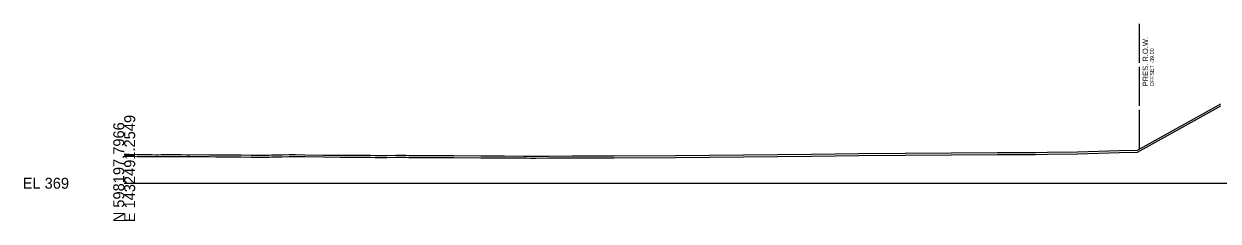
# Model space of a CAD drawing. Extents: x -26 to 2203, y -10 to 12201.
# Drawn here: x -25.7 to 280.1, y 2490.3 to 2540.8 of the extents above; entities that cross this region are included whole.
import ezdxf

# ---------------------------------------------------------------- set-up
doc = ezdxf.new("R2010")
doc.units = 0
for name, color, linetype in [('DESIGN - SHEET - Light Grid', 7, 'Continuous'), ('SURVEY - GROUND - Bottom of Topsoil Layer', 7, 'Continuous'), ('SURVEY - GROUND - Top of Ground', 7, 'Continuous'), ('SURVEY - PROPERTY - ROW Lines', 7, 'Continuous'), ('SURVEY - PROPERTY - ROW Lines Text', 7, 'Continuous')]:
    doc.layers.add(name, color=color, linetype=linetype)

msp = doc.modelspace()

# ---------------------------------------------------------------- linework, layer by layer
at = {"layer": 'DESIGN - SHEET - Light Grid'}
msp.add_line((0, 2500), (300, 2500), dxfattribs=at)
at = {"layer": 'SURVEY - GROUND - Bottom of Topsoil Layer'}
for p, q in [((279.4, 2519.05), (280.82, 2519.85)), ((259.41, 2507.96), (279.4, 2519.05)), ((233.3, 2507.33), (236.44, 2507.43)), ((236.44, 2507.43), (244.11, 2507.56)), ((244.11, 2507.56), (254.72, 2507.84)), ((254.72, 2507.84), (259.41, 2507.96)), ((0, 2506.92), (0.36, 2506.91)), ((0.36, 2506.91), (0.67, 2506.9)), ((0.67, 2506.9), (1.31, 2506.9)), ((1.31, 2506.9), (3.32, 2506.88)), ((3.32, 2506.88), (4.28, 2506.86)), ((4.28, 2506.86), (6.24, 2506.84)), ((6.24, 2506.84), (7.01, 2506.83)), ((7.01, 2506.83), (8.2, 2506.81)), ((8.2, 2506.81), (8.62, 2506.81)), ((8.62, 2506.81), (9.49, 2506.83)), ((9.49, 2506.83), (11.27, 2506.86)), ((11.27, 2506.86), (13.58, 2506.85)), ((13.58, 2506.85), (14.08, 2506.85)), ((14.08, 2506.85), (14.54, 2506.84)), ((14.54, 2506.84), (16.04, 2506.81)), ((16.04, 2506.81), (16.84, 2506.81)), ((16.84, 2506.81), (19.22, 2506.84)), ((19.22, 2506.84), (21.77, 2506.81)), ((21.77, 2506.81), (23.44, 2506.8)), ((23.44, 2506.8), (24.52, 2506.77)), ((24.52, 2506.77), (25.86, 2506.77)), ((25.86, 2506.77), (27.17, 2506.77)), ((27.17, 2506.77), (27.8, 2506.77)), ((27.8, 2506.77), (29.95, 2506.75)), ((29.95, 2506.75), (32.47, 2506.67)), ((32.47, 2506.67), (34.04, 2506.65)), ((34.04, 2506.65), (35.13, 2506.65)), ((35.13, 2506.65), (35.64, 2506.67)), ((35.64, 2506.67), (37.12, 2506.71)), ((37.12, 2506.71), (37.78, 2506.73)), ((37.78, 2506.73), (38.13, 2506.74)), ((38.13, 2506.74), (40.43, 2506.8)), ((40.43, 2506.8), (42.22, 2506.83)), ((42.22, 2506.83), (43.08, 2506.83)), ((43.08, 2506.83), (43.88, 2506.83)), ((43.88, 2506.83), (46.22, 2506.81)), ((46.22, 2506.81), (51.03, 2506.72)), ((51.03, 2506.72), (55.25, 2506.7)), ((55.25, 2506.7), (56.33, 2506.69)), ((56.33, 2506.69), (57.21, 2506.71)), ((57.21, 2506.71), (58.98, 2506.7)), ((58.98, 2506.7), (59.7, 2506.69)), ((59.7, 2506.69), (61.63, 2506.68)), ((61.63, 2506.68), (63.09, 2506.66)), ((63.09, 2506.66), (64.28, 2506.63)), ((64.28, 2506.63), (65.05, 2506.62)), ((65.05, 2506.62), (67.23, 2506.61)), ((67.23, 2506.61), (69.58, 2506.65)), ((69.58, 2506.65), (70.93, 2506.67)), ((70.93, 2506.67), (72.23, 2506.66)), ((72.23, 2506.66), (72.89, 2506.63)), ((72.89, 2506.63), (74.87, 2506.56)), ((74.87, 2506.56), (77.01, 2506.57)), ((77.01, 2506.57), (78.39, 2506.56)), ((78.39, 2506.56), (80.91, 2506.61)), ((80.91, 2506.61), (82.84, 2506.6)), ((82.84, 2506.6), (84.36, 2506.61)), ((84.36, 2506.61), (91.32, 2506.53)), ((91.32, 2506.53), (93.44, 2506.51)), ((93.44, 2506.51), (94.18, 2506.52)), ((94.18, 2506.52), (97.33, 2506.48)), ((97.33, 2506.48), (102.29, 2506.47)), ((102.29, 2506.47), (103.04, 2506.47)), ((103.04, 2506.47), (104.04, 2506.44)), ((104.04, 2506.44), (105.48, 2506.45)), ((105.48, 2506.45), (108.66, 2506.46)), ((108.66, 2506.46), (114.64, 2506.51)), ((114.64, 2506.51), (116.79, 2506.53)), ((116.79, 2506.53), (125.46, 2506.53)), ((125.46, 2506.53), (141.18, 2506.59)), ((141.18, 2506.59), (175.95, 2506.9)), ((175.95, 2506.9), (188.07, 2507.12)), ((188.07, 2507.12), (223.59, 2507.35)), ((223.59, 2507.35), (233.3, 2507.33))]:
    msp.add_line(p, q, dxfattribs=at)
at = {"layer": 'SURVEY - GROUND - Top of Ground'}
for p, q in [((279.4, 2519.55), (280.82, 2520.35)), ((259.41, 2508.46), (279.4, 2519.55)), ((0, 2507.42), (0.36, 2507.41)), ((0.36, 2507.41), (0.67, 2507.4)), ((0.67, 2507.4), (1.31, 2507.4)), ((1.31, 2507.4), (3.32, 2507.38)), ((141.18, 2507.09), (175.95, 2507.4)), ((175.95, 2507.4), (188.07, 2507.62)), ((188.07, 2507.62), (223.59, 2507.85)), ((223.59, 2507.85), (233.3, 2507.83)), ((233.3, 2507.83), (236.44, 2507.93)), ((236.44, 2507.93), (244.11, 2508.06)), ((244.11, 2508.06), (254.72, 2508.34)), ((254.72, 2508.34), (259.41, 2508.46)), ((3.32, 2507.38), (4.28, 2507.36)), ((4.28, 2507.36), (6.24, 2507.34)), ((6.24, 2507.34), (7.01, 2507.33)), ((7.01, 2507.33), (8.2, 2507.31)), ((8.2, 2507.31), (8.62, 2507.31)), ((8.62, 2507.31), (9.49, 2507.33)), ((9.49, 2507.33), (11.27, 2507.36)), ((11.27, 2507.36), (13.58, 2507.35)), ((13.58, 2507.35), (14.08, 2507.35)), ((14.08, 2507.35), (14.54, 2507.34)), ((14.54, 2507.34), (16.04, 2507.31)), ((16.04, 2507.31), (16.84, 2507.31)), ((16.84, 2507.31), (19.22, 2507.34)), ((19.22, 2507.34), (21.77, 2507.31)), ((21.77, 2507.31), (23.44, 2507.3)), ((23.44, 2507.3), (24.52, 2507.27)), ((24.52, 2507.27), (25.86, 2507.27)), ((25.86, 2507.27), (27.17, 2507.27)), ((27.17, 2507.27), (27.8, 2507.27)), ((27.8, 2507.27), (29.95, 2507.25)), ((29.95, 2507.25), (32.47, 2507.17)), ((32.47, 2507.17), (34.04, 2507.15)), ((34.04, 2507.15), (35.13, 2507.15)), ((35.13, 2507.15), (35.64, 2507.17)), ((35.64, 2507.17), (37.12, 2507.21)), ((37.12, 2507.21), (37.78, 2507.23)), ((37.78, 2507.23), (38.13, 2507.24)), ((38.13, 2507.24), (40.43, 2507.3)), ((40.43, 2507.3), (42.22, 2507.33)), ((42.22, 2507.33), (43.08, 2507.33)), ((43.08, 2507.33), (43.88, 2507.33)), ((43.88, 2507.33), (46.22, 2507.31)), ((46.22, 2507.31), (51.03, 2507.22)), ((51.03, 2507.22), (55.25, 2507.2)), ((55.25, 2507.2), (56.33, 2507.19)), ((56.33, 2507.19), (57.21, 2507.21)), ((57.21, 2507.21), (58.98, 2507.2)), ((58.98, 2507.2), (59.7, 2507.19)), ((59.7, 2507.19), (61.63, 2507.18)), ((61.63, 2507.18), (63.09, 2507.16)), ((63.09, 2507.16), (64.28, 2507.13)), ((64.28, 2507.13), (65.05, 2507.12)), ((65.05, 2507.12), (67.23, 2507.11)), ((67.23, 2507.11), (69.58, 2507.15)), ((69.58, 2507.15), (70.93, 2507.17)), ((70.93, 2507.17), (72.23, 2507.16)), ((72.23, 2507.16), (72.89, 2507.13)), ((72.89, 2507.13), (74.87, 2507.06)), ((74.87, 2507.06), (77.01, 2507.07)), ((77.01, 2507.07), (78.39, 2507.06)), ((78.39, 2507.06), (80.91, 2507.11)), ((80.91, 2507.11), (82.84, 2507.1)), ((82.84, 2507.1), (84.36, 2507.11)), ((84.36, 2507.11), (91.32, 2507.03)), ((91.32, 2507.03), (93.44, 2507.01)), ((93.44, 2507.01), (94.18, 2507.02)), ((94.18, 2507.02), (97.33, 2506.98)), ((97.33, 2506.98), (102.29, 2506.97)), ((102.29, 2506.97), (103.04, 2506.97)), ((103.04, 2506.97), (104.04, 2506.94)), ((104.04, 2506.94), (105.48, 2506.95)), ((105.48, 2506.95), (108.66, 2506.96)), ((108.66, 2506.96), (114.64, 2507.01)), ((114.64, 2507.01), (116.79, 2507.03)), ((116.79, 2507.03), (125.46, 2507.03)), ((125.46, 2507.03), (141.18, 2507.09))]:
    msp.add_line(p, q, dxfattribs=at)
at = {"layer": 'SURVEY - PROPERTY - ROW Lines'}
for p, q in [((260, 2530.78), (260, 2540.78)), ((260, 2519.78), (260, 2529.78)), ((260, 2508.78), (260, 2518.78))]:
    msp.add_line(p, q, dxfattribs=at)

# ---------------------------------------------------------------- texts
at = {"layer": 'DESIGN - SHEET - Light Grid'}
for s, p in [('E 1432491.2549', (2.8, 2490)), ('N 598197.7966', (0, 2490))]:
    msp.add_text(s, height=2.8, rotation=90, dxfattribs=at).set_placement(p)
msp.add_text('EL 369', height=2.8, dxfattribs=at).set_placement((-26, 2498.6))
at = {"layer": 'SURVEY - PROPERTY - ROW Lines Text'}
for s, height, p in [('PRES. R.O.W.', 1.4, (262.15, 2524.78)), ('OFFSET -39.00', 1, (263.65, 2524.78))]:
    msp.add_text(s, height=height, rotation=90, dxfattribs=at).set_placement(p)

doc.saveas('drawing.dxf')
